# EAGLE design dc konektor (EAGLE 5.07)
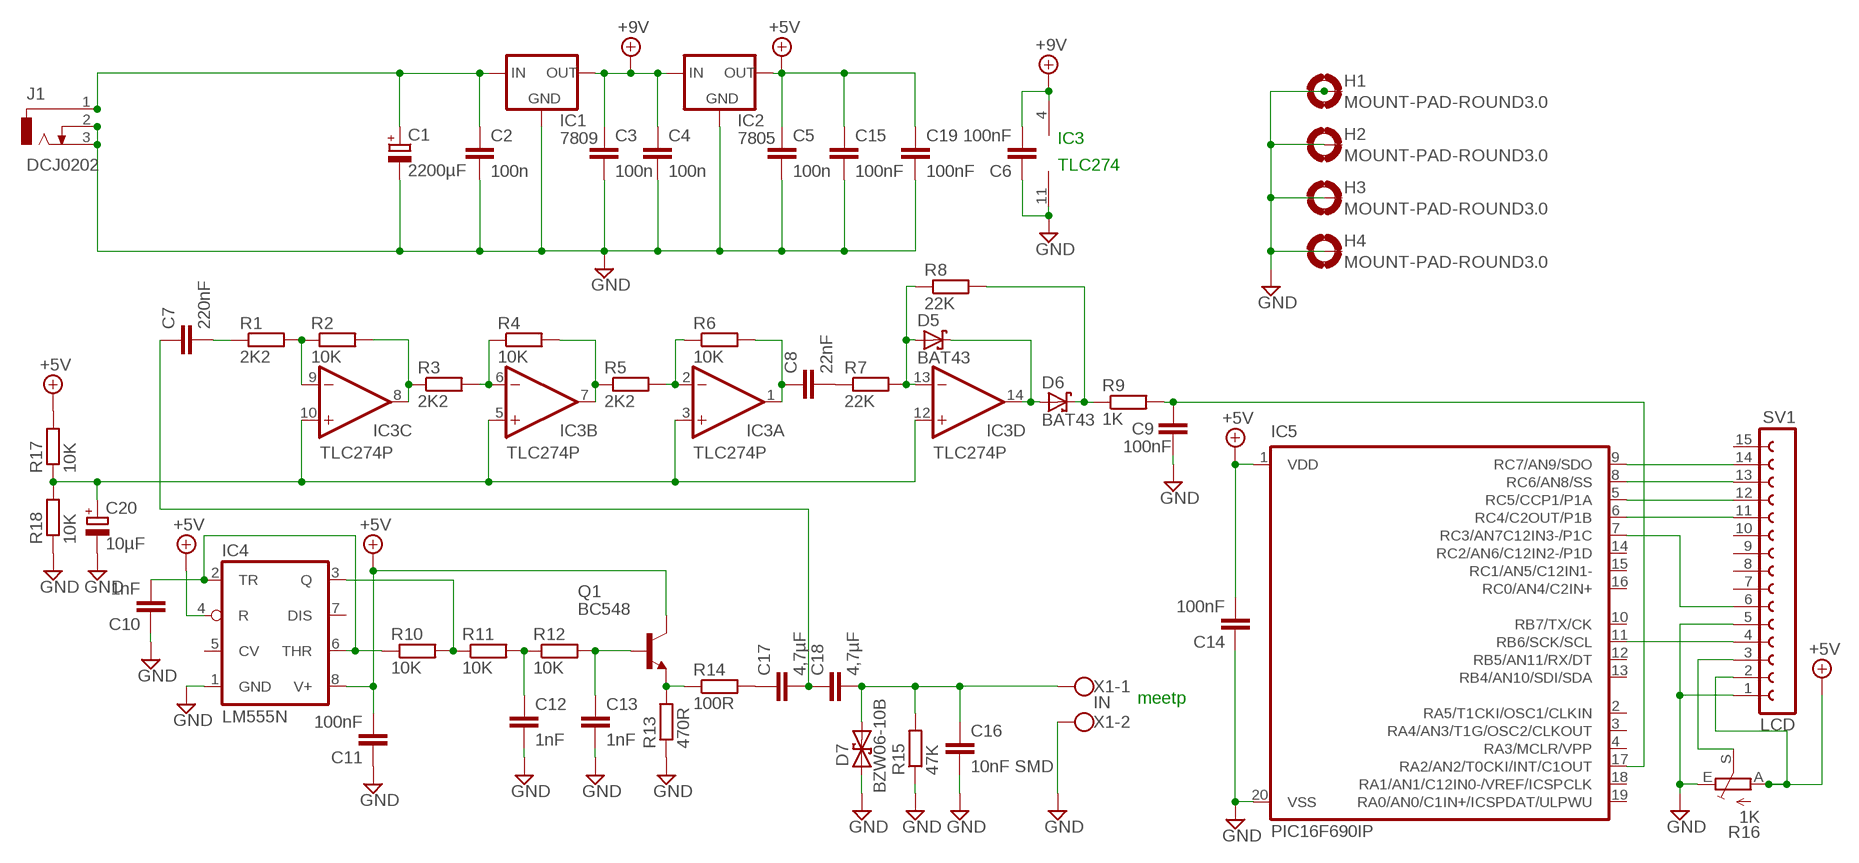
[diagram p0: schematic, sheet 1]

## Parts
C1  2200µF  CPOL-EUE7.5-18  [E7,5-18]
C2  100n  C-EU050-025X075  [C050-025X075]
C3  100n  C-EU050-025X075  [C050-025X075]
C4  100n  C-EU050-025X075  [C050-025X075]
C5  100n  C-EU050-025X075  [C050-025X075]
C6  100nF  C-EU050-025X075  [C050-025X075]
C7  220nF  C-EU050-025X075  [C050-025X075]
C8  22nF  C-EU050-025X075  [C050-025X075]
C9  100nF  C-EU050-025X075  [C050-025X075]
C10  1nF  C-EU050-025X075  [C050-025X075]
C11  100nF  C-EU050-025X075  [C050-025X075]
C12  1nF  C-EU050-025X075  [C050-025X075]
C13  1nF  C-EU050-025X075  [C050-025X075]
C14  100nF  C-EU050-025X075  [C050-025X075]
C15  100nF  C-EU050-025X075  [C050-025X075]
C16  10nF SMD  C-EU050-025X075  [C050-025X075]
C17  4,7µF  C-EU275-113X316  [C275-113X316]
C18  4,7µF  C-EU275-113X316  [C275-113X316]
C19  100nF  C-EU050-025X075  [C050-025X075]
C20  10µF  CPOL-EUE5-8.5  [E5-8,5]
D5  BAT43  BAT42  [DO35-10]
D6  BAT43  BAT42  [DO35-10]
D7  BZW06-10B  BZW04XXB  [F126Z12]
H1  MOUNT-PAD-ROUND3.0  [3,0-PAD]
H2  MOUNT-PAD-ROUND3.0  [3,0-PAD]
H3  MOUNT-PAD-ROUND3.0  [3,0-PAD]
H4  MOUNT-PAD-ROUND3.0  [3,0-PAD]
IC1  7809  78XXS  [78XXS]
IC2  7805  78XXS  [78XXS]
IC3  TLC274P  [DIL14]
IC4  LM555N  [DIL08]
IC5  PIC16F690IP  [DIL20]
J1  DCJ0202  [DCJ0202]
Q1  BC548  [TO92-EBC]
R1  2K2  R-EU_0204/7  [0204/7]
R2  10K  R-EU_0204/7  [0204/7]
R3  2K2  R-EU_0204/7  [0204/7]
R4  10K  R-EU_0204/7  [0204/7]
R5  2K2  R-EU_0204/7  [0204/7]
R6  10K  R-EU_0204/7  [0204/7]
R7  22K  R-EU_0204/7  [0204/7]
R8  22K  R-EU_0204/7  [0204/7]
R9  1K  R-EU_0204/7  [0204/7]
R10  10K  R-EU_0204/7  [0204/7]
R11  10K  R-EU_0204/7  [0204/7]
R12  10K  R-EU_0204/7  [0204/7]
R13  470R  R-EU_0204/7  [0204/7]
R14  100R  R-EU_0204/7  [0204/7]
R15  47K  R-EU_0204/7  [0204/7]
R16  1K  TRIM_EU-S63P  [S63P]
R17  10K  R-EU_0204/7  [0204/7]
R18  10K  R-EU_0204/7  [0204/7]
SV1  LCD  FE15-1  [FE15]
X1  IN  W237-102  [W237-102]

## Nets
+5V: C5.1 C11.2 C14.2 C15.1 C19.1 IC2.OUT IC4.4(R) IC4.8(V+) IC5.1(VDD) Q1.C R16.A R17.2 SV1.2
+9V: C3.1 C4.1 C6.2 IC1.OUT IC2.IN IC3.4(P:V+)
GND: C1.- C2.2 C3.2 C4.2 C5.2 C6.1 C9.1 C10.1 C11.1 C12.2 C13.2 C14.1 C15.2 C16.2 C19.2 C20.- D7.A H1.B3,0(MOUNT) H2.B3,0(MOUNT) H3.B3,0(MOUNT) H4.B3,0(MOUNT) IC1.GND IC2.GND IC3.11(P:V-) IC4.1(GND) IC5.20(VSS) J1.2 J1.3 R13.1 R15.1 R16.E R18.1 SV1.1 SV1.5 X1.2
N$2: C1.+ C2.1 IC1.IN J1.1
N$6: IC3.8(C:OUT) R2.2 R3.1
N$7: IC3.6(B:-IN) R3.2 R4.1
N$8: C7.2 R1.1
N$9: IC3.9(C:-IN) R1.2 R2.1
N$10: IC3.7(B:OUT) R4.2 R5.1
N$11: IC5.9(RC7/AN9/SDO) SV1.14
N$13: C8.2 R7.1
N$14: D5.A IC3.13(D:-IN) R7.2 R8.1
N$15: D5.C D6.A IC3.14(D:OUT)
N$16: D6.C R8.2 R9.1
N$17: C9.2 IC5.17(RA2/AN2/T0CKI/INT/C1OUT) R9.2
N$18: C10.2 IC4.2(TR) IC4.6(THR) R10.1
N$19: IC4.3(Q) R10.2 R11.1
N$20: C12.1 R11.2 R12.1
N$21: C13.1 Q1.B R12.2
N$22: Q1.E R13.2 R14.1
N$23: C17.1 R14.2
N$24: IC3.2(A:-IN) R5.2 R6.1
N$25: C7.1 C17.2 C18.1
N$26: C16.1 C18.2 D7.C R15.2 X1.1
N$27: IC5.8(RC6/AN8/SS) SV1.13
N$28: IC5.5(RC5/CCP1/P1A) SV1.12
N$29: IC5.6(RC4/C2OUT/P1B) SV1.11
N$30: IC5.11(RB6/SCK/SCL) SV1.4
N$31: IC5.7(RC3/AN7C12IN3-/P1C) SV1.6
N$32: C8.1 IC3.1(A:OUT) R6.2
N$35: C20.+ IC3.3(A:+IN) IC3.5(B:+IN) IC3.10(C:+IN) IC3.12(D:+IN) R17.1 R18.2
N$37: R16.S SV1.3
Unconnected: IC4.5(CV) IC4.7(DIS) IC5.2(RA5/T1CKI/OSC1/CLKIN) IC5.3(RA4/AN3/T1G/OSC2/CLKOUT) IC5.4(RA3/MCLR/VPP) IC5.10(RB7/TX/CK) IC5.12(RB5/AN11/RX/DT) IC5.13(RB4/AN10/SDI/SDA) IC5.14(RC2/AN6/C12IN2-/P1D) IC5.15(RC1/AN5/C12IN1-) IC5.16(RC0/AN4/C2IN+) IC5.18(RA1/AN1/C12IN0-/VREF/ICSPCLK) IC5.19(RA0/AN0/C1IN+/ICSPDAT/ULPWU) SV1.7 SV1.8 SV1.9 SV1.10 SV1.15

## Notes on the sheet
- IC3
- TLC274
- meetp

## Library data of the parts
C1 C20 = rcl:CPOL-EU: POLARIZED CAPACITOR, European symbol
C2-C19 = rcl:C-EU: CAPACITOR, European symbol
D5 D6 = diode:BAT42: DIODE
D7 = diode:BZW04XXB: DIODE
H1-H4 = holes:MOUNT-PAD-ROUND: MOUNTING PAD, round
IC1 IC2 = v-reg:78XXS: VOLTAGE REGULATOR
IC3 = linear:TLC274: OP AMP
IC4 = linear:*555: TIMER
IC5 = microchip-5:PIC16F690*: MICROCONTROLLER PIC16F690 18 I/O One 16-bit timer Two 8-bit timer Two comparators Precision internal oscillator-software selectable 8 MHz - 32 KHz SSP w/ I2C Compatible Address mask option EUSART LIN 2.0 Compatible ECCP+ w/ PWM Steering 12 A/D Channels ULPW Enhanced Low Power Timer 1 Timer 1 Gate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
J1 = con-jack:DCJ0202: DC POWER JACK Source: DCJ0202.pdf
Q1 = transistor-npn:BC548*: NPN Transistor
R1-R15 R17 R18 = rcl:R-EU_: RESISTOR, European symbol
R16 = pot:TRIM_EU-: POTENTIOMETER
SV1 = con-lsta:FE15-1: FEMALE HEADER
X1 = con-wago-500:W237-102: WAGO SCREW CLAMP

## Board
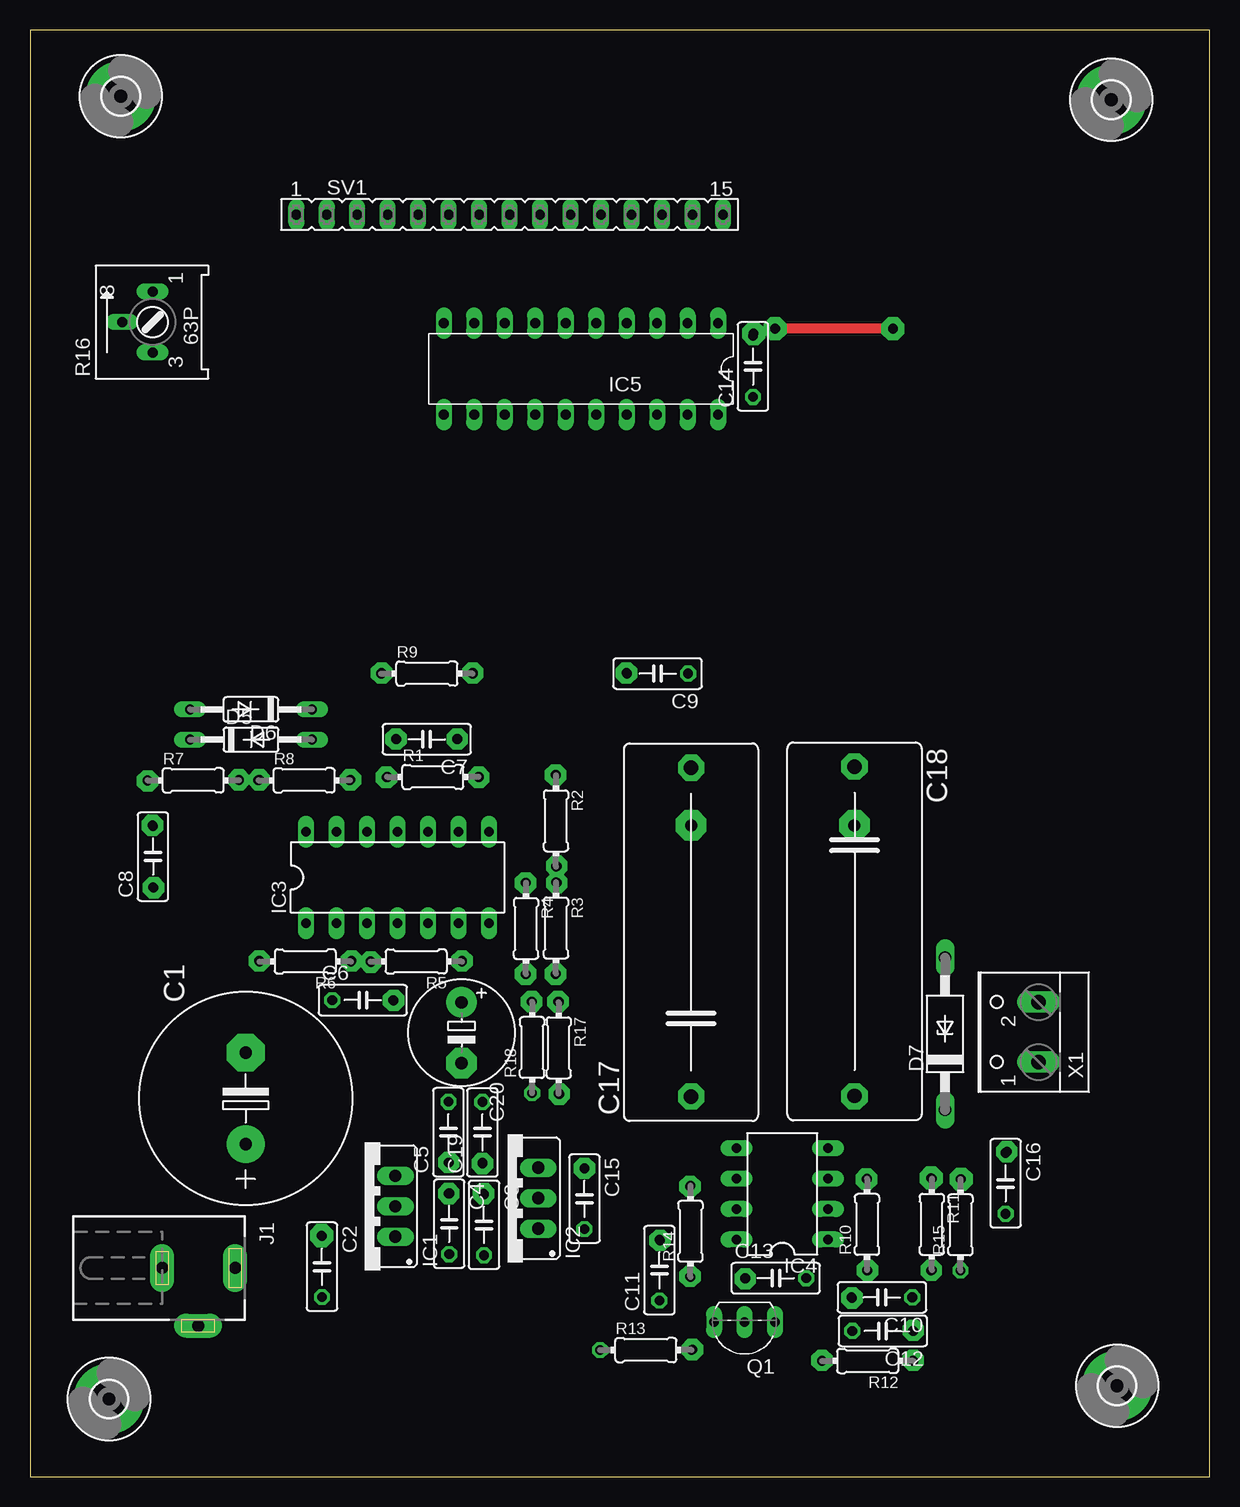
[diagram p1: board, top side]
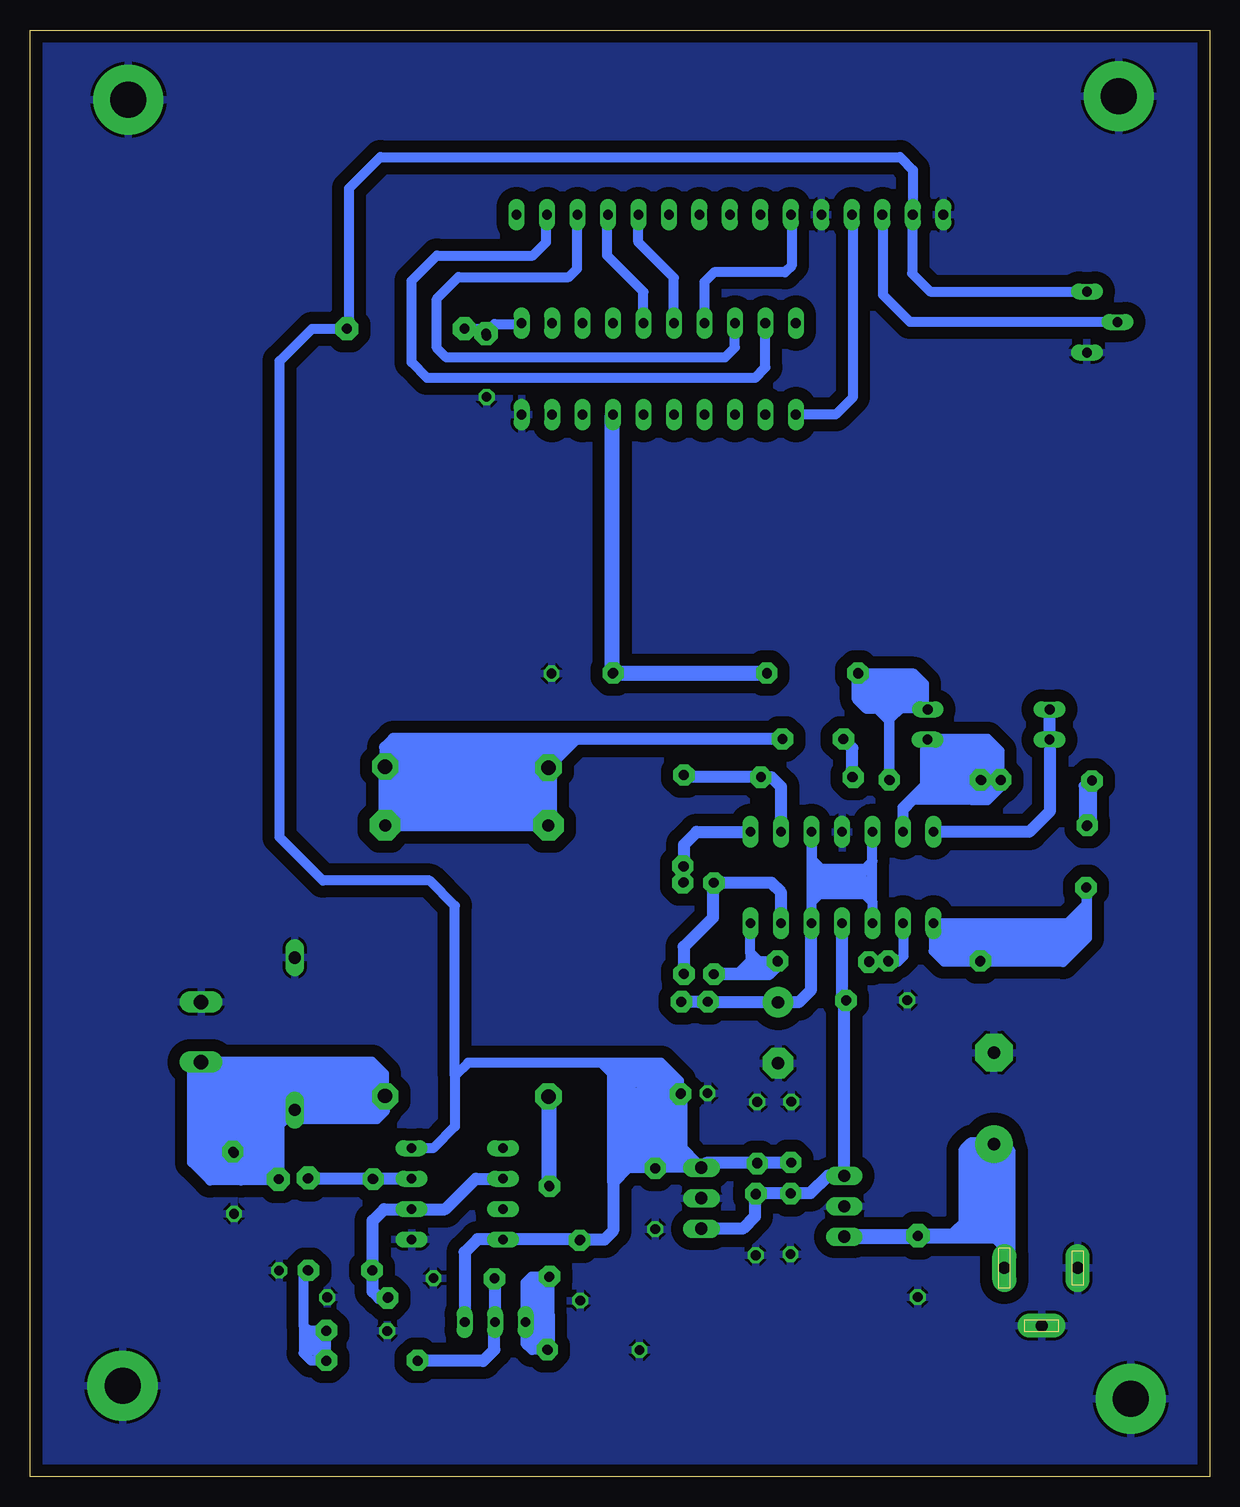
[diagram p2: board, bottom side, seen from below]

Size 98.3 x 120.6 mm. Coordinates in mm from the lower left corner, seen from the top.
Outline: 0,0 98.3,0 98.3,120.6 0,120.6 0,0
Copper layers (1*16): Top 0.035mm / dielectric 1.5mm / Bottom 0.035mm
Design rules "default": minimum track width 10mil, minimum drill 24mil, track to track 8mil, track to pad 8mil, pad to pad 8mil, via to via 8mil, smd to smd 8mil, copper to edge 40mil, drill to drill 8mil, minimum pad ring 10mil, minimum via ring 8mil, stop-mask expansion 4mil, vias tented up to drill 0mil, thermal gap 10mil

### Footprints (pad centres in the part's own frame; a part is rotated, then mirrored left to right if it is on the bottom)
E7,5-18 = drill 1.016 pad 3.15 round: + -3.81,0 | drill 1.016 pad 3.15 octagon: - 3.81,0
C050-025X075 = drill 0.813 octagon: 1 -2.54,0; 2 2.54,0
C275-113X316 = drill 1.194 octagon: 1 -13.716,0; 2 13.716,0
E5-8,5 = drill 1.016 pad 2.54 round: + -2.54,0 | drill 1.016 pad 2.54 octagon: - 2.54,0
DO35-10 = drill 0.813 long: A 5.08,0; C -5.08,0
F126Z12 = drill 1.016 long: A 6.35,0; C -6.35,0
3,0-PAD = drill 3 pad 5.842 round: B3,0 0,0
78XXS = drill 1.016 long: GND 0,-2.54; IN -2.54,-2.54; OUT 2.54,-2.54
DIL14 = drill 0.813 long: 1 -7.62,-3.81; 2 -5.08,-3.81; 3 -2.54,-3.81; 4 0,-3.81; 5 2.54,-3.81; 6 5.08,-3.81; 7 7.62,-3.81; 8 7.62,3.81; 9 5.08,3.81; 10 2.54,3.81; 11 0,3.81; 12 -2.54,3.81; 13 -5.08,3.81; 14 -7.62,3.81
DIL08 = drill 0.813 long: 1 -3.81,-3.81; 2 -1.27,-3.81; 3 1.27,-3.81; 4 3.81,-3.81; 5 3.81,3.81; 6 1.27,3.81; 7 -1.27,3.81; 8 -3.81,3.81
DIL20 = drill 0.813 long: 1 -11.43,-3.81; 2 -8.89,-3.81; 3 -6.35,-3.81; 4 -3.81,-3.81; 5 -1.27,-3.81; 6 1.27,-3.81; 7 3.81,-3.81; 8 6.35,-3.81; 9 8.89,-3.81; 10 11.43,-3.81; 11 11.43,3.81; 12 8.89,3.81; 13 6.35,3.81; 14 3.81,3.81; 15 1.27,3.81; 16 -1.27,3.81; 17 -3.81,3.81; 18 -6.35,3.81; 19 -8.89,3.81; 20 -11.43,3.81
DCJ0202 = drill 1 pad 2 long: 1 0,3.1; 2 4.8,0; 3 0,-3
TO92-EBC = drill 0.813 long: B 0,-1.27; C -2.54,-1.27; E 2.54,-1.27
0204/7 = drill 0.813 octagon: 1 -3.81,0; 2 3.81,0
S63P = drill 0.813 long: A 2.54,0; E -2.54,0; S 0,2.54
FE15 = drill 0.813 long: 1 -17.78,0; 2 -15.24,0; 3 -12.7,0; 4 -10.16,0; 5 -7.62,0; 6 -5.08,0; 7 -2.54,0; 8 0,0; 9 2.54,0; 10 5.08,0; 11 7.62,0; 12 10.16,0; 13 12.7,0; 14 15.24,0; 15 17.78,0
W237-102 = drill 1.194 long: 1 -2.5,-1.27; 2 2.5,-1.27

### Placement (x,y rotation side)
C1  17.97,31.54 90 top
C2  24.33,17.51 270 top
C3  37.83,21 270 top
C4  34.93,21.09 270 top
C5  34.87,28.72 90 top
C6  27.73,39.73 0 top
C7  33.06,61.47 180 top
C8  10.25,51.69 90 top
C9  52.3,66.95 180 top
C10  70.99,14.95 180 top
C11  52.45,17.22 90 top
C12  71.07,12.15 180 top
C13  62.14,16.55 0 top
C14  60.25,92.55 90 top
C15  46.2,23.18 270 top
C16  81.3,24.46 270 top
C17  55.09,45.39 90 top
C18  68.71,45.46 270 top
C19  37.7,28.7 90 top
C20  35.96,37.01 270 top
D5  18.42,61.45 0 top
D6  18.41,63.96 180 top
D7  76.25,36.92 90 top
H1  7.57,115.08 0 top
H2  6.58,6.48 0 top
H3  90.59,7.58 0 top
H4  90.1,114.78 0 top
IC1  27.91,22.55 90 top
IC2  39.81,23.22 90 top
IC3  30.63,49.95 0 top
IC4  62.69,23.58 90 top
IC5  45.91,92.35 180 top
J1  14,17.4 270 top
Q1  59.54,11.62 180 top
R1  33.58,58.33 0 top
R2  43.83,54.68 270 top
R3  43.83,45.74 270 top
R4  41.33,45.7 270 top
R5  32.18,42.95 180 top
R6  22.94,42.95 180 top
R7  13.6,58.05 0 top
R8  22.84,58.05 0 top
R9  33.08,66.95 0 top
R10  69.75,21.02 90 top
R11  75.15,21.04 270 top
R12  69.8,9.65 180 top
R13  51.32,10.56 0 top
R14  55.04,20.46 90 top
R15  77.54,21 90 top
R16  10.22,96.25 90 top
R17  44.06,35.76 270 top
R18  41.84,35.78 90 top
SV1  39.97,105.21 0 top
X1  82.77,37.06 90 top

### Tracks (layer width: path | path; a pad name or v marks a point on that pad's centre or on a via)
+5V  (via drill 0.6, 0.8 pad 1.78, 0.8 pad 1.93)
  Top 0.813: v72,95.7 v71.9,95.7 v62.2,95.7
  Bottom 0.813: 37.68,26.18 C19.1 | 41.95,26.16 IC2.OUT 45.76,25.76 | IC4.8 58.91,19.8 | 45.76,25.76 C15.1 45.82,25.7 v46.2,25.7 48.6,25.7 | 45.76,25.76 45.76,31.15 R17.2 44.2,32.09 44.2,33 45.7,34.5 61.8,34.5 62.9,33.4 | C11.2 | IC4.4 64.71,27.39 62.9,29.2 62.9,33.4 | 62.9,33.4 62.9,47.6 65,49.7 73.9,49.7 77.5,53.3 77.5,93 74.8,95.7 v72,95.7 71.7,96 71.7,107.4 69.1,110 25.8,110 24.73,108.93 SV1.2 24.8,105.14 24.8,100.3 23.29,98.79 R16.A | IC5.1 57.41,96.09 59.61,96.09 60,95.7 60,95.4 | v62.2,95.7 v62.19,95.69 60.29,95.69 60,95.4 | 60,95.4 60,95.14 C14.2 | 49.7,33.5 50.6,34.4
  Bottom 1.016: C5.1 37.68,26.18 | C19.1 41.95,26.16 | Q1.C 62.08,18.72 61,19.8 58.91,19.8 | C11.2 50.44,19.76 49.7,20.5 49.7,24.6 | 48.6,25.7 49.7,24.6 | C11.2 IC4.8 | 49.7,24.6 49.7,33.5
+9V  (via drill 0.8 pad 1.78)
  Bottom 0.813: IC1.OUT | 37.74,23.63 C3.1 37.9,23.47 | 30.46,39.54 v30.3,39.7 C6.2 30.63,40.09
  Bottom 1.016: 37.74,23.63 C4.1 33.27,23.63 31.8,25.1 IC1.OUT 30.46,39.54 | IC2.IN 38.92,20.68 37.9,21.7 37.9,23.47 | 30.63,40.09 IC3.4
GND
  pour Bottom (isolate 1.016): 0,120.9 98.4,120.9 98.3,0.4 0,0.4
N$2
  Bottom 1.27: IC1.IN 24.37,20.01 C2.1 17.75,20.05 17,19.3 17,18.4 | 17,18.4 17,17.5 J1.1 | C1.+ 17.43,27.73 16.8,27.1 16.8,18.6 17,18.4
N$4
  Bottom 1.27: 17.9,27.7 19.8,27.7 20.3,27.2 20.3,21.1 21.2,20.2
N$5  (via drill 0.8 pad 1.78)
  other vias: 17.4,58.1
N$6
  Bottom 0.813: 43.8,50.9 R2.2 R3.1
  Bottom 1.016: IC3.8 42.74,53.76 43.8,52.7 43.8,50.9
N$7
  Bottom 0.813: IC3.6 | R4.1 41.4,49.44
  Bottom 1.016: R4.1 36.51,49.51 35.7,48.7 IC3.6 | R3.2 43.83,44.17 41.4,46.6 41.4,49.44
N$8
  Bottom 1.016: R1.1 29.77,60.72 C7.2
N$9
  Bottom 0.813: 37.36,58.3 R1.2 | 43.67,58.33 R2.1
  Bottom 1.016: IC3.9 35.71,57.51 36.5,58.3 37.36,58.3 | R1.2 43.67,58.33
N$10
  Bottom 0.813: R5.1 37.55,42.95 38.3,43.7 | IC3.7 38.3,45.89 38.3,43.7 | R4.2 39.01,41.89 38.3,42.6 38.3,43 | 38.3,43.7 38.3,43 | 41.1,42 39.3,42 38.3,43
N$11
  Bottom 0.813: IC5.9 37.02,92.48 37.9,91.6 65.2,91.6 66.5,92.9 66.5,99.7 64.4,101.8 56.4,101.8 55.3,102.9 55.3,105.12 SV1.14
N$12
  Bottom 0.813: 17.5,58.3 17.5,60.5 18.5,61.5 23,61.5
N$13
  Bottom 0.813: R7.1 9.79,54.69 C8.2
N$14
  Bottom 0.813: IC3.13 25.55,55.55 24.7,56.4 19.8,56.4 | 19.1,57.1 19,57.2 19,58.02 R8.1 18.1,58.05 | 19.1,57.1 19.8,56.4 | R7.2 18.1,58.05 | D5.A 19.05,61.45 18.3,60.7 18.3,58.25 18.1,58.05 | 19.8,56.4 18.5,56.4 17.4,57.5 17.4,57.7 17.5,57.8 | 19.1,57.1 18.2,57.1 17.9,57.4 18.3,57.4 18.5,57.6
N$15
  Bottom 0.813: 13.3,60.59 D5.C | D6.A
  Bottom 1.016: IC3.14 15.04,53.76 13.3,55.5 13.3,60.59 | D5.C D6.A
N$16
  Bottom 0.813: R8.2 26.65,63.15 25.7,64.1 23.63,64.1 D6.C 23.8,64.27 23.8,66.1 24.65,66.95 R9.1
N$17
  Bottom 0.813: 49.76,88.5 IC5.17
  Bottom 1.27: R9.2 C9.2 49.76,88.5
N$18  (via drill 0.8 pad 1.78)
  Bottom 0.813: IC4.2 | R10.1 69.79,17.25 | C10.2 v68.5,14.9
  Bottom 1.016: IC4.2 68.8,22.3 69.75,21.35 R10.1 69.75,15.45 69.2,14.9 v68.5,14.9 | IC4.6 61.15,24.85 63.7,22.3 IC4.2
N$19
  Bottom 0.813: 69.73,24.85 R10.2 | 75.13,24.83 R11.1
  Bottom 1.016: IC4.3 69.73,24.85 | R10.2 75.13,24.83
N$20  (via drill 0.8 pad 1.78)
  Bottom 0.813: R12.1 C12.1 75.05,12.15 75.5,12.6 | 75.5,12.6 75.5,16.88 R11.2 | 75.5,12.6 75.5,10.3 74.9,9.7 v73.6,9.7
N$21
  Bottom 0.813: 59.54,16.49 C13.1 | 59.6,12.83 Q1.B
  Bottom 1.016: Q1.B 59.54,16.49 | R12.2 60.55,9.65 59.6,10.6 59.6,12.83
N$22
  Bottom 0.813: 55,13.6 55.71,12.89 Q1.E 57,11.1 56.46,10.56 R13.2 | 55,13.6 55,16.61 R14.1 | 55,13.6 55,10.9
N$23
  Bottom 0.813: 55.04,31.62 C17.1
  Bottom 1.27: R14.2 55.04,31.62
N$24
  Bottom 0.813: R5.2 R6.1 25.95,42.95 25.5,43.4 25.5,46.09 IC3.2
N$25
  Bottom 0.813: C7.1 52.73,61.47 C17.2 55.16,59.18 C18.1
N$26
  Bottom 0.813: C18.2 75.08,31.74 D7.C | R15.2 77.54,29.28 D7.C | C16.1 81.3,29.7 80.1,30.9 76.58,30.9 D7.C | X1.1 77.36,34.56 76.2,33.4 76.2,31.2 76.3,31.1 76.3,30.62 D7.C
N$27
  Bottom 0.813: IC5.8 39.56,94.14 40.4,93.3 63.6,93.3 64.4,94.1 64.4,98.2 62.6,100 53.4,100 52.7,100.7 52.7,105.18 SV1.13
N$28
  Bottom 0.813: IC5.5 47.18,98.78 50.2,101.8 50.2,105.14 SV1.12
N$29
  Bottom 0.813: IC5.6 44.64,99.94 47.6,102.9 SV1.11
N$30
  Bottom 0.813: IC5.11 31.16,88.54 29.7,90 29.7,105.1 SV1.4
N$31
  Bottom 0.813: IC5.7 42.1,99.6 41.3,100.4 35.4,100.4 34.8,101 34.8,105.12 SV1.6
N$32  (via drill 0.8 pad 1.78)
  Bottom 0.813: 19.1,42.9 12.2,42.9 10.2,44.9 10.2,48.8 10.3,48.9 | 10.3,48.9 10.3,47.7 11.86,46.14 IC3.1 23,43.8 22.15,42.95 R6.2 | 10.3,48.9 v10.3,49.1 C8.1
N$33
  Bottom 0.813: 10.5,46.9 11.8,45.6 22.2,45.6 22.5,45.3 22.5,44.3 21.9,43.7 12.4,43.7 10.7,45.4 10.7,45.8 11.3,45.8 12.9,44.2 21.4,44.2 22.1,44.9 13.1,44.9 12.6,45.4
N$34
  Bottom 0.813: 41,41.8 36.7,41.8 36,42.5 36,42.9
N$35
  Bottom 0.813: 33.17,47.93 IC3.5 33.2,45.97 | 33.17,47.93 32.5,48.6 28.8,48.6 28.1,47.9 | 28.1,47.9 IC3.3 | 33.17,47.93 IC3.10 33.17,51.47 32.4,50.7 28.7,50.7 28.1,51.3 IC3.12 | 42.5,39.55 R18.2 | 28.1,47.9 28.1,53.3 28.2,53.4
  Bottom 1.016: 33.2,45.97 33.2,40.6 34.25,39.55 C20.+ 42.5,39.55 | R17.1 42.56,39.57 R18.2
N$36
  Bottom 0.813: 36.5,42.5 37.6,42.5 37.8,42.3
N$37
  Bottom 0.813: R16.S 24.95,96.25 27.2,98.5 27.2,105.14 SV1.3
N$38
  Bottom 0.813: 23.7,61.5 23.7,57.7 25.6,55.8 25.6,53.9
N$39
  Bottom 0.813: 24.1,57 20.1,57 19.6,57.5 19.6,58.5 19,59.1 19,59.6 18.9,59.7 | 18.9,59.7 18.9,59.4 | 18.9,59.4 18.9,59 | 18.9,59.7 18.9,60.4 19.6,61.1 23.2,61.1 23.2,57.6 23.4,57.4 20.5,57.4 20.2,57.7 20.2,58.3 | 20.2,58.3 20.2,60.2 20.5,60.5 20,60.5 19.9,60.6 19.8,60.6 19.4,60.2 19.4,59.5 19.8,59.1 | 19.8,59.1 19.8,59 | 19.8,59.1 19.8,59.6 20.7,60.5 22.8,60.5 22.8,59.3 22.7,59.2 22.7,58.1 22.5,57.9 21.1,57.9 20.9,58.1 20.4,58.1 20.2,58.3 | 20.2,58.3 22.3,58.3 22.4,58.2 22.4,58.4 22.6,58.6 21,58.6 20.7,58.9 21.8,58.9 22.1,59.2 20.3,59.2 19.9,59.6 23,59.6 23.1,59.5 20.7,59.5 20.3,59.9 22.3,59.9 22.4,60 19.5,60 18.9,59.4
N$40
  Bottom 0.813: 28.6,50.5 32.2,50.5 32.8,49.9 32.8,49.3 32.6,49.1 28.5,49.1 28.5,49.5 28.7,49.7 32,49.7 32.1,49.6 31.5,49.6 31.3,49.8 31.2,49.8 31.2,49.9 31.6,49.9 31.7,50
N$45
  Bottom 0.813: 55.3,11 55.6,11.3 56.4,11.3 56.5,11.4 56.5,12.1 56.3,12.3 56.1,12.3 56,12.4 55.5,12.4 55.7,12.2 55.7,11.6 55.9,11.8 55.9,11.9
N$46
  Bottom 0.813: 74.2,10 74.2,11.5 74.9,11.5 75,11.6 75,10.9 74.6,10.5 74.6,11.2
N$47
  Bottom 0.813: 77.7,24.7 80.7,24.7 | 80.7,24.7 81.4,25.4 81.4,26.7 81.3,26.8 | 80.7,24.7 83.3,24.7 84.8,26.2 84.8,33.7 84.2,34.3
N$48
  Bottom 0.813: 81.6,26.8 83.8,26.8 84.6,27.6 84.6,33.6 83.9,34.3
N$49
  Bottom 0.813: 76.1,29.8 69.4,29.8 68.7,30.5 68.7,31.1 68.8,31.2
N$50
  Bottom 0.813: 69.1,31.2 75,31.2 76.1,30.1 69.7,30.1 69.2,30.6 74.9,30.6 75.1,30.4
N$51
  Bottom 0.813: 83.9,34.6 69.8,34.6 68.8,33.6 68.8,31.6
N$52
  Bottom 0.813: 69.4,31.9 69.4,33.4 70,34 83.3,34 84,33.3 70.1,33.3 69.9,33.1 69.9,32.9 69.8,32.8 84.2,32.8 84.3,32.7 84.3,32.3 84.2,32.2 69.6,32.2 69.5,32.3 75,32.3 75.9,31.4 84.2,31.4 84.2,31.3 84.1,31.2 84.1,27.9 83.7,27.5 82,27.5 81.8,27.3 81.8,28.1 | 81.8,28.1 81.8,29.3 81.5,29.6 81.5,29.8 80.4,30.9 83,30.9 83.2,30.7 83.5,30.7 83.6,30.8 83.6,29.6 | 83.6,29.6 83.6,28.5 83.5,28.4 83.5,28.2 81.9,28.2 81.8,28.1 | 81.8,28.1 82.2,28.1 | 82.2,28.1 82.5,28.1 83.4,29 82.4,29 82.3,29.1 83.1,29.1 83.6,29.6 | 83.6,29.6 82.2,29.6 82,29.8 83.2,29.8 83.4,30 81.5,30 81.1,30.4 82.6,30.4 82.6,28.5 82.2,28.1
N$53
  Bottom 0.813: 77.8,25 80.2,25 81,25.8 81,29.1 80.1,30 77.3,30 77.2,30.1 77.2,30.3 79.9,30.3
N$54
  Bottom 0.813: 78.1,25.3 78.1,29.5 79.7,29.5 80.5,28.7 80.5,26.4 79.8,25.7 78.7,25.7 78.7,29 78.8,29.1 79.3,29.1 79.6,28.8 79.6,26.3 79.5,26.2 79.2,26.2 79.1,26.3 79.1,28.6 79.2,28.7 79.9,28.7 80,28.8 80,26.7 79.8,26.5
N$55
  Bottom 0.813: 81.3,25.8 83.8,25.8 84.4,26.4 82.1,26.4 82,26.5 81.9,26.5 81.3,25.9 81.3,25.6 81.6,25.3 82.9,25.3 83.2,25.6
N$56
  Bottom 0.813: 26.7,58.5 26.7,63 27.7,64 28.6,64 29.4,64.8 29.4,66.5 29.2,66.7
N$57
  Bottom 0.813: 24.3,66.3 28.9,66.3 29.2,66 29.2,65.4 28.9,65.1 24.3,65.1 24,65.4 24.2,65.6 28.6,65.6 28.7,65.5 28.7,64.7 28.8,64.6 24.6,64.6 | 24.6,64.6 24.2,64.6 | 24.6,64.6 25,64.2 26.7,64.2 26.9,64 27.1,64
N$58
  Bottom 1.016: 35.7,61.5 68,61.5 68.7,60.8 68.7,59.4
N$59
  Bottom 0.813: 53.8,61.1 67.5,61.1 68.3,60.3 68.3,59.9 55,59.9 54.3,60.6 67.1,60.6 67.7,60
N$62
  Bottom 0.813: 43.9,31.9 43.9,27.4 42.6,26.1 45,26.1 45.2,26.3 45.2,30.7 45.1,30.8 44.9,30.8 44.5,31.2 44.5,26.8 44.6,26.7 43.6,26.7 43.5,26.6
N$63
  Bottom 0.813: 49.2,25.8 49.2,33.9 49.4,34.1 46,34.1 45,33.1 45,32.9 44.7,32.6 44.7,32.2 44.8,32.1 45.3,32.1 46.1,31.3 46.1,26.8 46.4,26.5 48.5,26.5 48.7,26.3 48.7,33.3 48.4,33.6 46.2,33.6 45.3,32.7 45.4,32.7 46.1,32 46.1,32.5 46.5,32.9 48.1,32.9 48.2,33 48.2,27 47.7,27 | 47.7,27 46.9,27 46.8,27.1 46.8,32 46.5,32.3 47.4,32.3 47.4,27.3 47.7,27 | 47.7,27 47.7,29.7 46.4,31 46.4,31.5 46.3,31.6
N$64  (via drill 0.8 pad 1.93)
  other vias: 62.1,95.7
N$65  (via drill 0.8 pad 1.93)
  other vias: 60.3,95.3
N$66  (via drill 1 pad 2.18)
  other vias: 55.1,59.1
N$67  (via drill 1 pad 2.18)
  other vias: 68.7,59.2
N$68  (via drill 1 pad 2.18)
  other vias: 68.7,31.7
N$69  (via drill 1 pad 2.18)
  other vias: 55.1,31.7
N$72
  Bottom 1.27: 19.7,20.5 19.7,26.4 19.5,26.6 17.6,26.6 17.6,20.7 18.6,20.7 18.8,20.9 18.8,25.2 19.3,25.7 18.8,25.7 18.5,26
N$74  (via drill 0.8 pad 1.78)
  other vias: 28.4,42.9
N$75  (via drill 0.8 pad 1.78)
  other vias: 26.8,43
N$76  (via drill 0.8 pad 1.78)
  other vias: 36,43
N$77  (via drill 0.8 pad 1.78)
  other vias: 19.1,43
N$78  (via drill 0.8 pad 1.78)
  other vias: 41.8,39.6
N$79  (via drill 0.8 pad 1.78)
  other vias: 44,39.6
N$80  (via drill 0.8 pad 1.78)
  other vias: 43.8,41.9
N$81  (via drill 0.8 pad 1.78)
  other vias: 41.3,41.9
N$82  (via drill 0.8 pad 1.78)
  other vias: 44.1,31.9
N$83  (via drill 0.8 pad 1.78)
  other vias: 37.7,26.1
N$84  (via drill 0.8 pad 1.78)
  other vias: 34.9,26.2
N$85  (via drill 0.8 pad 1.78)
  other vias: 37.8,23.6
N$86  (via drill 0.8 pad 1.78)
  other vias: 34.9,23.6
N$87
  Bottom 0.813: 57,12.9 57,16.2 56.5,16.7 55.2,16.7
N$88
  Bottom 0.813: 56.3,13 56.3,16 55.6,16 55.4,16.2 55.4,13.6 55.8,13.2 55.8,15.4 55.7,15.5
N$89  (via drill 0.8 pad 1.78)
  other vias: 59.6,16.5
N$90  (via drill 0.8 pad 1.78)
  other vias: 19.1,58.1
N$91  (via drill 0.8 pad 1.78)
  other vias: 26.7,58.1
N$92  (via drill 0.8 pad 1.78)
  other vias: 29.7,58.3
N$93  (via drill 0.8 pad 1.78)
  other vias: 37.4,58.3
N$94  (via drill 0.8 pad 1.78)
  other vias: 35.6,61.5
N$95  (via drill 0.8 pad 1.78)
  other vias: 30.5,61.5
N$96  (via drill 0.8 pad 1.78)
  other vias: 29.3,67
N$97  (via drill 0.8 pad 1.78)
  other vias: 36.9,67
N$98  (via drill 0.8 pad 1.78)
  other vias: 43.8,58.5
N$99  (via drill 0.8 pad 1.78)
  other vias: 43.9,50.9
N$100  (via drill 0.8 pad 1.78)
  other vias: 43.9,49.5
N$101  (via drill 0.8 pad 1.78)
  other vias: 41.3,49.5
N$102  (via drill 0.8 pad 1.78)
  other vias: 49.7,67
N$104  (via drill 0.8 pad 1.78)
  other vias: 55,24.2
N$105  (via drill 0.8 pad 1.78)
  other vias: 55,16.7
N$106  (via drill 0.8 pad 1.78)
  other vias: 52.5,19.7
N$107  (via drill 0.8 pad 1.78)
  other vias: 55.2,10.6
N$108  (via drill 0.8 pad 1.78)
  other vias: 66,9.7
N$109  (via drill 0.8 pad 1.78)
  other vias: 73.6,12.2
N$110  (via drill 0.8 pad 1.78)
  other vias: 69.8,17.2
N$111  (via drill 0.8 pad 1.78)
  other vias: 75.1,17.2
N$112  (via drill 0.8 pad 1.78)
  other vias: 69.7,24.8
N$113  (via drill 0.8 pad 1.78)
  other vias: 81.4,27.1
N$114  (via drill 0.8 pad 1.78)
  other vias: 9.8,58
N$115  (via drill 0.8 pad 1.78)
  other vias: 10.2,54.3
N$116  (via drill 0.8 pad 1.93)
  other vias: 24.3,20.1
N$117
  Bottom 0.813: 10.5,54.3 10.5,57.6 10.1,58
N$118  (via drill 0.8 pad 1.93)
  other vias: 75.1,24.9
N$119  (via drill 0.8 pad 1.93)
  other vias: 77.6,24.8
N$120  (via drill 1 pad 2.54)
  other vias: 55.1,54.3
N$121  (via drill 1 pad 2.54)
  Bottom 1.016: 54.9,54.2 54.9,58.8 55.1,59 55.3,59 | 55.3,59 55.4,58.9 55.4,54.8 55.1,54.5 | 55.1,54.5 55.1,54.4 | 55.1,54.6 55.1,54.5 | 55.1,57.2 55.1,58.8 55.3,59 | v68.7,54.3 55.4,54.3 55.1,54.6 | 55.1,57.2 55.1,54.6 | 55.1,57.2 56.6,58.7 67.4,58.7 68.1,58 68.1,55.5 67.6,55 56.3,55 55.8,55.5 66.8,55.5 67.4,56.1 56.3,56.1 56,56.4 66.8,56.4 67.4,57 56.3,57 56,57.3 67,57.3 67.3,57.6 56.8,57.6 56.4,58 67.3,58 67.4,57.9
N$123
  Bottom 1.016: 68.4,54.2 68.4,58.7 68.8,59.1 68.8,54.3 68.9,54.2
